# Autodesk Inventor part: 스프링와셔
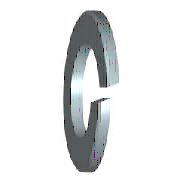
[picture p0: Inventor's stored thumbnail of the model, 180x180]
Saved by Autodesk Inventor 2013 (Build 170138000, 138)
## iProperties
Created: 2012-02
Part Number: 스프링와셔
Material: 강철, 연강
Description: 스프링 와셔
Document SubType Name: Modeling
Standard: JIS B 1251
Designer: mduedu
Standards Organization: JIS
Language: ko-KR
Size Designation: 번호 2 4
Categories: <MemberInstance><Categories><Category DisplayName="조임쇠" InternalName="e4da775c-781d-43d5-af7c-5136215cf5a6" Mnemonic="FSTN"><Category DisplayName="와셔" InternalN
Density: 7.86 g/cm^3
Mass: 0.247271 g
Surface Area: 1.02615 cm^2
Volume: 0.0314594 cm^3
IsCustomPart: 1
Author: mduedu
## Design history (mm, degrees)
sketch "스케치1"
  geometry: C1 r 3.8 at (0, 0); C2 r 2.05 at (0, 0); 1 further point
  constraints: 2 centre point, 2 coincident
  dimensions: "d0" = 4.1 diameter of C2 (= SD1); "d1" = 7.6 diameter of C1 (= SD2)
extrude "본체" new body sketch "스케치1" distance "d2" = 1 (= SD); taper "d3" = 0 deg
sketch "스케치2"
  geometry: L1 (0, -2.05)-(0, 2.05) reference; L2 (1, 3.8)-(1, -3.8) reference; L3 (-1.2, 0)-(7.2, 0) reference; L4 (0, -0.2)-(1, 0.164); L5 (0, 0.2)-(1, 0.564)
  constraints: 4 end point, 4 point on line, 1 parallel
  dimensions: "d4" = 0.2 distance from line of L3 L4.start (= 0.2 x SD); "d5" = 0.2 distance from line of L3 L5.start (= 0.2 x SD); "d6" = 70 deg angle of L2 L4 (= FAWI)
extrude "절단부" cut sketch "스케치2" stored distance "d7" = 1 (= SD); taper "d8" = 0 deg
workaxis "Work Axis1"
workplane "Work Plane1"
body "Solid1"
other parameters: "SD1" = 4.1 [user parameter; used in 1 equation term], "SD2" = 7.6 [user parameter; used in 1 equation term], "SD" = 1 [user parameter; used in 4 equation terms], "FAWI" = 70 deg [user parameter; used in 1 equation term], "d9" = 0, "d10" = 0, "d11" = 0, "d12" = 0, "SDI" = 1.4 [user parameter], "NND" = 4 [user parameter]
